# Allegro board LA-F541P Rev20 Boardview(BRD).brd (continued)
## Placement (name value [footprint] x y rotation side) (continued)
PC1910  4.7U_0402_6.3V6M  [C_0402]  48.62 10.21 180 top
PC1911  1U 25V K X5R 0402  [C_0402]  48.58 9.32 270 top
PC1912  1U 25V K X5R 0402  [C_0402]  47.69 9.32 270 top
PC1913  0.22U_0603_25V7K  [C_0603]  44.07 8.7 90 top
PC1914  10U_0603_25V6M  [C_0603]  33.83 27.81 90 bottom
PC1915  10U_0603_25V6M  [C_0603]  35.05 27.81 90 bottom
PC1916  10U_0603_25V6M  [C_0603]  35.05 27.81 90 top
PC1917  10U_0603_25V6M  [C_0603]  36.32 27.81 90 bottom
PC1918  10U_0603_25V6M  [C_0603]  37.59 27.81 90 bottom
PC1919  10U_0603_25V6M  [C_0603]  36.32 27.81 90 top
PC1920  10U_0603_25V6M  [C_0603]  33.83 27.81 90 top
PC1921  10U_0603_25V6M  [C_0603]  32.61 27.81 90 top
PC1922  10U_0603_25V6M  [C_0603]  32.61 27.81 90 bottom
PC1923  0.1U_0402_25V6  [C_0402]  43.82 24.21 270 bottom
PC1924  2200P_0402_50V7K  [C_0402]  43.82 21.51 90 bottom
PC1925  0.1U 25V K X5R 0402  [C_0402]  53.52 13.54 270 bottom
PC1926  1U_0603_25V6  [C_0603]  52.45 12.19 90 top
PC1927  1U_0402_6.3V6K  [C_0402]  41.71 10.16 0 top
PC1928  1U_0402_6.3V6K  [C_0402]  53.96 14.86 0 top
PC1929  0.22U_0603_25V7K  [C_0603]  43.5 12.45 180 top
PC1930  10U_0603_25V6M  [C_0603]  27 23.67 270 bottom
PC1931  10U_0603_25V6M  [C_0603]  28.45 25.91 0 bottom
PC1932  2200P_0402_50V7K  [C_0402]  31.48 17.1 270 bottom
PC1933  4700P_0402_25V7K  [C_0402]  42.67 19.43 180 top
PC1934  10P_0402_50V8J  [C_0402]  52.76 19.75 0 top
PC1935  0.1U_0402_25V6  [C_0402]  42.37 14.86 180 top
PC1936  680P_0402_50V7K  [C_0402]  38.48 6.73 0 top
PC1937  680P_0402_50V7K  [C_0402]  33.34 13.03 270 top
PC1938  1U 25V K X5R 0402  [C_0402]  42.37 15.88 180 top
PC1939  560P_0402_50V7K  [C_0402]  47.83 20.56 90 top
PC1940  0.1U_0402_25V6  [C_0402]  45.28 20.5 90 top
PC1941  0.012U_0402_16V7K  [C_0402]  48.76 20.56 90 top
PC1942  1U_0402_25V6K  [C_0402]  43.31 17.6 270 top
PC1943  0.22U_0402_25V6K  [C_0402]  42.37 18.42 180 top
PC1944  0.1U_0402_10V7K  [C_0402]  62.69 16.45 180 top
PC1945  0.1U_0402_25V6  [C_0402]  41.77 20.38 0 top
PC2000  22U_0603_6.3VAM  [C_0603]  175.85 92.39 90 bottom
PC2001  470U_D2_2VM_R4.5M~D  [C_D2]  156.08 100.59 180 bottom
PC2002  470U_D2_2VM_R4.5M~D  [C_D2]  158.22 95.89 0 bottom
PC2003  22U_0603_6.3VAM  [C_0603]  150.49 105.57 90 top
PC2004  1U_0201_6.3V6M  [C_0201]  156.22 73.23 0 top
PC2005  1U_0201_6.3V6M  [C_0201]  162.74 86.88 0 top
PC2006  1U_0201_6.3V6M  [C_0201]  160.81 85.9 180 top
PC2007  1U_0201_6.3V6M  [C_0201]  161.19 69.61 180 top
PC2008  1U_0201_6.3V6M  [C_0201]  167.76 69.59 0 top
PC2009  1U_0201_6.3V6M  [C_0201]  155.29 81.18 180 top
PC2010  22U_0603_6.3VAM  [C_0603]  146.8 105.71 90 top
PC2011  220U_D7_2VM_R6M  [C_EEFSS0D221R]  161.4 77.22 0 top
PC2012  22U_0603_6.3VAM  [C_0603]  161.25 80.46 180 top
PC2013  22U_0603_6.3VAM  [C_0603]  157.28 84.72 0 top
PC2014  22U_0603_6.3VAM  [C_0603]  157.28 74.21 0 top
PC2015  22U_0603_6.3VAM  [C_0603]  160.68 83.01 180 top
PC2016  22U_0603_6.3VAM  [C_0603]  166.17 80.49 180 top
PC2017  22U_0603_6.3VAM  [C_0603]  166.6 71.19 180 top
PC2018  22U_0603_6.3VAM  [C_0603]  161.77 71.19 180 top
PC2019  470U_D2_2VM_R4.5M~D  [C_D2]  118.14 76.76 180 bottom
PC2020  470U_D2_2VM_R4.5M~D  [C_D2]  123.19 74.96 270 bottom
PC2021  22U_0603_6.3VAM  [C_0603]  145.82 70.63 180 top
PC2022  22U_0603_6.3VAM  [C_0603]  120.14 71.18 270 top
PC2023  22U_0603_6.3VAM  [C_0603]  146.71 78.24 0 top
PC2024  22U_0603_6.3VAM  [C_0603]  145.76 78.2 180 top
PC2025  22U_0603_6.3VAM  [C_0603]  151.7 79.83 0 top
PC2026  22U_0603_6.3VAM  [C_0603]  151.69 81.08 0 top
PC2027  22U_0603_6.3VAM  [C_0603]  151.42 76.57 0 top
PC2028  220U_D7_2VM_R6M  [C_EEFSS0D221R]  154.33 100.59 180 top
PC2029  1U_0201_6.3V6M  [C_0201]  157.92 85.64 0 top
PC2030  1U_0201_6.3V6M  [C_0201]  162.8 81.38 0 top
PC2031  1U_0201_6.3V6M  [C_0201]  156.23 72.01 0 top
PC2032  1U_0201_6.3V6M  [C_0201]  163.08 70.25 0 top
PC2033  1U_0201_6.3V6M  [C_0201]  167.79 70.22 0 top
PC2034  1U_0201_6.3V6M  [C_0201]  156.21 71.43 0 top
PC2035  1U_0201_6.3V6M  [C_0201]  165.96 70.22 180 top
PC2036  1U_0201_6.3V6M  [C_0201]  161.15 70.29 180 top
PC2037  1U_0201_6.3V6M  [C_0201]  165.73 81.37 180 top
PC2038  1U_0201_6.3V6M  [C_0201]  161.27 83.92 180 top
PC2039  22U_0603_6.3VAM  [C_0603]  161.64 74.13 180 top
PC2040  22U_0603_6.3VAM  [C_0603]  162.37 97.79 0 top
PC2041  22U_0603_6.3VAM  [C_0603]  158.6 77.68 90 top
PC2042  1U_0201_6.3V6M  [C_0201]  162.75 86.31 0 top
PC2043  1U_0201_6.3V6M  [C_0201]  157.9 87.41 0 top
PC2044  1U_0201_6.3V6M  [C_0201]  156.22 69.54 0 top
PC2045  1U_0201_6.3V6M  [C_0201]  156.51 86.25 180 top
PC2046  1U_0201_6.3V6M  [C_0201]  157.58 81.48 0 top
PC2047  1U_0201_6.3V6M  [C_0201]  167.7 84.9 0 top
PC2048  1U_0201_6.3V6M  [C_0201]  165.93 84.19 180 top
PC2049  1U_0201_6.3V6M  [C_0201]  165.56 85.09 180 top
PC2050  1U_0201_6.3V6M  [C_0201]  160.82 84.69 180 top
PC2051  1U_0201_6.3V6M  [C_0201]  161.92 83.81 0 top
PC2052  1U_0201_6.3V6M  [C_0201]  157.9 86.23 0 top
PC2053  1U_0201_6.3V6M  [C_0201]  160.91 81.97 180 top
PC2054  1U_0201_6.3V6M  [C_0201]  167.71 84.2 0 top
PC2055  1U_0201_6.3V6M  [C_0201]  162.73 85.09 0 top
PC2056  1U_0201_6.3V6M  [C_0201]  156.22 72.64 0 top
PC2057  1U_0201_6.3V6M  [C_0201]  167.72 85.68 0 top
PC2058  1U_0201_6.3V6M  [C_0201]  167.63 86.83 0 top
PC2059  1U_0201_6.3V6M  [C_0201]  165.56 86.25 180 top
PC2060  1U_0201_6.3V6M  [C_0201]  165.57 86.85 180 top
PC2061  1U_0201_6.3V6M  [C_0201]  160.81 86.48 180 top
PC2062  1U_0201_6.3V6M  [C_0201]  160.94 81.38 180 top
PC2063  1U_0201_6.3V6M  [C_0201]  167.61 81.38 0 top
PC2064  1U_0201_6.3V6M  [C_0201]  162.74 85.7 0 top
PC2065  1U_0201_6.3V6M  [C_0201]  156.25 70.78 0 top
PC2066  1U_0201_6.3V6M  [C_0201]  161.92 84.39 0 top
PC2067  1U_0201_6.3V6M  [C_0201]  165.96 69.59 180 top
PC2068  1U_0201_6.3V6M  [C_0201]  157.89 86.83 0 top
PC2069  1U_0201_6.3V6M  [C_0201]  160.81 85.3 180 top
PC2070  1U_0201_6.3V6M  [C_0201]  156.24 70.15 0 top
PC2071  1U_0201_6.3V6M  [C_0201]  163.08 69.67 0 top
PC2072  1U_0201_6.3V6M  [C_0201]  165.58 85.67 180 top
PC2073  1U_0201_6.3V6M  [C_0201]  167.63 86.26 0 top
PC2074  1U_0201_6.3V6M  [C_0201]  152.08 85.82 0 top
PC2075  1U_0201_6.3V6M  [C_0201]  145.33 69.72 180 top
PC2076  1U_0201_6.3V6M  [C_0201]  152.02 69.74 0 top
PC2077  1U_0201_6.3V6M  [C_0201]  152.01 84.51 0 top
PC2078  1U_0201_6.3V6M  [C_0201]  151.94 83.26 0 top
PC2079  1U_0201_6.3V6M  [C_0201]  151.59 87.87 0 top
PC2080  1U_0201_6.3V6M  [C_0201]  145.25 68.73 270 top
PC2081  1U_0201_6.3V6M  [C_0201]  146.19 68.67 270 top
PC2082  1U_0201_6.3V6M  [C_0201]  153.21 69.74 0 top
PC2083  1U_0201_6.3V6M  [C_0201]  144.15 69.13 90 top
PC2084  1U_0201_6.3V6M  [C_0201]  147.06 68.69 270 top
PC2085  1U_0201_6.3V6M  [C_0201]  152.95 68.91 0 top
PC2086  22U_0603_6.3VAM  [C_0603]  162.37 99.06 0 top
PC2087  22U_0603_6.3VAM  [C_0603]  157.39 76.68 270 top
PC2088  22U_0603_6.3VAM  [C_0603]  162.37 100.33 0 top
PC2089  22U_0603_6.3VAM  [C_0603]  162.39 82.92 0 top
PC2090  22U_0603_6.3VAM  [C_0603]  151.72 105.55 90 top
PC2091  22U_0603_6.3VAM  [C_0603]  146.88 79.83 0 top
PC2092  22U_0603_6.3VAM  [C_0603]  146.58 76.55 0 top
PC2093  22U_0603_6.3VAM  [C_0603]  151.78 73.57 0 top
PC2094  22U_0603_6.3VAM  [C_0603]  146.86 81.08 0 top
PC2095  22U_0603_6.3VAM  [C_0603]  153.53 105.4 90 top
PC2096  22U_0603_6.3VAM  [C_0603]  162.36 80.49 0 top
PC2097  22U_0603_6.3VAM  [C_0603]  167.61 71.19 0 top
PC2098  22U_0603_6.3VAM  [C_0603]  167.18 80.49 0 top
PC2099  22U_0603_6.3VAM  [C_0603]  160.85 100.33 0 bottom
PC2100  22U_0603_6.3VAM  [C_0603]  160.85 99.06 0 bottom
PC2101  22U_0603_6.3VAM  [C_0603]  162.79 71.19 0 top
PC2102  22U_0603_6.3VAM  [C_0603]  160.85 101.6 0 bottom
PC2103  22U_0603_6.3VAM  [C_0603]  167.15 82.91 0 top
PC2104  22U_0603_6.3VAM  [C_0603]  167.61 72.43 0 top
PC2105  22U_0603_6.3VAM  [C_0603]  166.19 82.9 180 top
PC2106  22U_0603_6.3VAM  [C_0603]  162.79 72.42 0 top
PC2107  22U_0603_6.3VAM  [C_0603]  161.84 72.42 180 top
PC2108  22U_0603_6.3VAM  [C_0603]  167.42 74.07 0 top
PC2109  22U_0603_6.3VAM  [C_0603]  166.46 74.13 180 top
PC2110  22U_0603_6.3VAM  [C_0603]  162.65 74.13 0 top
PC2111  22U_0603_6.3VAM  [C_0603]  166.59 72.42 180 top
PC2112  22U_0603_6.3VAM  [C_0603]  158.66 76.68 270 top
PC2113  22U_0603_6.3VAM  [C_0603]  157.03 80.56 0 top
PC2114  22U_0603_6.3VAM  [C_0603]  145.34 105.74 90 top
PC2115  22U_0603_6.3VAM  [C_0603]  156.89 83.05 0 top
PC2116  22U_0603_6.3VAM  [C_0603]  144.03 105.77 90 top
PC2117  22U_0603_6.3VAM  [C_0603]  157.33 77.68 90 top
PC2118  22U_0603_6.3VAM  [C_0603]  123.95 71.18 270 top
PC2119  22U_0603_6.3VAM  [C_0603]  122.68 71.18 270 top
PC2120  22U_0603_6.3VAM  [C_0603]  121.41 71.18 270 top
PC2121  22U_0603_6.3VAM  [C_0603]  150.77 70.63 180 top
PC2122  22U_0603_6.3VAM  [C_0603]  146.96 70.63 0 top
PC2123  22U_0603_6.3VAM  [C_0603]  151.47 78.22 0 top
PC2124  22U_0603_6.3VAM  [C_0603]  150.45 78.22 180 top
PC2125  22U_0603_6.3VAM  [C_0603]  151.79 70.63 0 top
PC2126  22U_0603_6.3VAM  [C_0603]  151.75 72.29 0 top
PC2127  22U_0603_6.3VAM  [C_0603]  150.73 72.29 180 top
PC2128  22U_0603_6.3VAM  [C_0603]  146.92 72.29 0 top
PC2129  22U_0603_6.3VAM  [C_0603]  145.78 72.29 180 top
PC2130  22U_0603_6.3VAM  [C_0603]  150.64 73.57 180 top
PC2131  22U_0603_6.3VAM  [C_0603]  150.69 79.83 180 top
PC2132  22U_0603_6.3VAM  [C_0603]  150.67 81.08 180 top
PC2133  22U_0603_6.3VAM  [C_0603]  150.4 76.57 180 top
PC2134  22U_0603_6.3VAM  [C_0603]  146.83 73.57 0 top
PC2135  22U_0603_6.3VAM  [C_0603]  145.69 73.57 180 top
PC2136  22U_0603_6.3VAM  [C_0603]  145.57 76.55 180 top
PC2137  22U_0603_6.3VAM  [C_0603]  145.86 79.83 180 top
PC2138  22U_0603_6.3VAM  [C_0603]  145.85 81.08 180 top
PC2139  22U_0603_6.3VAM  [C_0603]  171.58 76.14 180 top
PC2140  22U_0603_6.3VAM  [C_0603]  171.58 74.93 180 top
PC2141  22U_0603_6.3VAM  [C_0603]  171.58 77.34 180 top
PC2142  22U_0603_6.3VAM  [C_0603]  171.58 78.61 180 top
PC2143  22U_0603_6.3VAM  [C_0603]  171.66 73.69 180 top
PC2144  22U_0603_6.3VAM  [C_0603]  117.86 88.2 270 top
PC2145  22U_0603_6.3VAM  [C_0603]  116.59 88.2 270 top
PC2146  22U_0603_6.3VAM  [C_0603]  117.86 88.2 270 bottom
PC2147  22U_0603_6.3VAM  [C_0603]  115.32 88.2 270 bottom
PC2148  22U_0603_6.3VAM  [C_0603]  116.59 88.2 270 bottom
PC2149  22U_0603_6.3VAM  [C_0603]  115.32 88.2 270 top
PC2150  22U_0603_6.3VAM  [C_0603]  170.82 92.39 90 bottom
PC2151  22U_0603_6.3VAM  [C_0603]  172.09 92.39 90 bottom
PC2152  22U_0603_6.3VAM  [C_0603]  173.36 92.39 90 bottom
PC2153  22U_0603_6.3VAM  [C_0603]  174.63 92.39 90 bottom
PD100  AZ5125-01H.R7G_SOD523-2  [AZ5125-01HPR7G_SOD523-2]  28.32 82.05 90 top
PD101  -  [TVNST52302AB0_SOT523-3]  14.1 10.23 0 top
PD102  -  [TVNST52302AB0_SOT523-3]  21.34 3.11 180 top
PD200  SDT8A100P5-13D_POWERDI5-3  [PDS1040-13_POWERDI5-3]  15.24 20.07 90 bottom
PD201  SDT8A100P5-13D_POWERDI5-3  [PDS1040-13_POWERDI5-3]  20.24 20.07 90 bottom
PD202  -  [RB751V-40_SOD323-2]  21.78 10.67 180 top
PD203  -  [RB520SM-30T2R_EMD2-2]  66.97 22.54 225 top
PD204  -  [RB520SM-30T2R_EMD2-2]  64.83 25.33 225 top
PD1900  -  [RB751V-40_SOD323-2]  57.28 16.38 270 top
PD1902  -  [RB751V-40_SOD323-2]  59.79 15.93 270 top
PD1903  -  [BAT54CW_SOT323-3]  62.5 11.99 0 top
PD1904  SMF4L22A SOD123FL-2  [SMF22A-SOD123FL-2-S]  58.01 6.59 270 bottom
PH1100  470K_0402_5%_ TSM0B474J4702RE  [R_0402]  105.16 85.66 270 bottom
PH1101  10K_0402_5%_B25/50 4250K  [R_0402]  114.99 92.67 180 bottom
PH1102  10K_0402_5%_B25/50 4250K  [R_0402]  121.22 85.92 180 bottom
PH1103  10K_0402_5%_B25/50 4250K  [R_0402]  146.53 101.79 0 bottom
PH1104  470K_0402_5%_ TSM0B474J4702RE  [R_0402]  145.29 103.04 180 bottom
PJP200  -  [JUMP_43X118]  25.86 27.93 180 top
PJP400  -  [JUMP_43X118]  318.58 11.3 0 top
PJP402  PAD-OPEN 4X4M  [JUMP_43X118]  324.71 25.33 180 top
PJP403  PAD-OPEN 4X4M  [JUMP_43X118]  318.02 5.71 180 top
PJP500  -  [JUMP_43X118]  120.83 7.03 90 bottom
PJP600  -  [JUMP_43X118]  279.59 31.28 180 bottom
PJP601  PAD-OPEN1X1M  [JUMP_43X39]  283.15 30.93 0 bottom
PJP602  PAD-OPEN 3X3M  [JUMP_43X79]  283.02 29.4 270 top
PJP603  PAD-OPEN 4X4M  [JUMP_43X118]  256.73 25.7 270 bottom
PJP701  -  [JUMP_43X118]  216.24 118.24 0 bottom
PJP702  -  [JUMP_43X118]  216.24 118.24 0 top
PJP800  -  [JUMP_43X118]  117.22 63.95 0 bottom
PJP900  PAD-OPEN1X1M  [JUMP_43X39]  224.64 116.21 0 bottom
PJP1301  -  [JUMP_43X118]  109.28 98.74 90 bottom
PJP1302  PAD-OPEN 3X3M  [JUMP_43X79]  115.22 11.89 180 bottom
PJP1303  PAD-OPEN 3X3M  [JUMP_43X79]  118.49 12.53 90 bottom
PJP1600  -  [JUMP_43X118]  244.6 97.32 270 bottom
PJP1604  PAD-OPEN 3X3M  [JUMP_43X79]  164.09 51.22 270 top
PL104  BLM15AG102SN1D_2P  [MURAT_BLM15AG102SN1D_2P]  26.39 82.44 90 top
PL105  HCB2012KF-800T50_2P  [TAI-T_HCB2012KF-800T50_2P]  25.78 86.77 0 bottom
PL106  HCB2012KF-800T50_2P  [TAI-T_HCB2012KF-800T50_2P]  25.78 88.63 0 bottom
PL107  HCB2012KF-800T50_2P  [TAI-T_HCB2012KF-800T50_2P]  30.32 16.68 180 bottom
PL108  HCB2012KF-800T50_2P  [TAI-T_HCB2012KF-800T50_2P]  26.62 18.97 270 bottom
PL200  HCB2012KF-800T50_2P  [TAI-T_HCB2012KF-800T50_2P]  30.9 28 180 top
PL201  HCB2012KF-800T50_2P  [TAI-T_HCB2012KF-800T50_2P]  30.9 29.83 180 top
PL400  3.3UH_PCMB063T-3R3MS_6.5A_20%  [CYNTE_PCMB063T-3R3MS_2P]  331.3 28.52 0 top
PL401  2.2UH_PCMB103T-2R2MS_13A_20%  [CYNTE_PCMB103T-2R2MS_2P]  337.82 7.45 180 top
PL402  HCB2012KF-800T50_2P  [TAI-T_HCB2012KF-800T50_2P]  318.26 14.83 0 top
PL403  HCB2012KF-800T50_2P  [TAI-T_HCB2012KF-800T50_2P]  318.26 16.7 0 top
PL500  HCB2012KF-800T50_2P  [TAI-T_HCB2012KF-800T50_2P]  138.98 12.46 270 bottom
PL501  1UH_PCMB053T-1R0MS_7A_20%  [CYNTE_PCMB053T-1R0MS_2P]  129.68 6.49 180 bottom
PL600  1UH_PCMB063T-1R0MS_12A_20%  [CYNTE_PCMB063T-1R0MS_2P]  262.53 32.26 0 bottom
PL601  HCB2012KF-800T50_2P  [TAI-T_HCB2012KF-800T50_2P]  279.56 27.75 180 bottom
PL700  0.82UH_MMD-06CZ-R82M-V1L_13A_20%  [L_7X7X3_M_2P]  201.95 116.33 0 bottom
PL777  HCB2012KF-800T50_2P  [TAI-T_HCB2012KF-800T50_2P]  196.72 113.25 270 top
PL800  HCB2012KF-800T50_2P  [TAI-T_HCB2012KF-800T50_2P]  105.39 56.9 0 bottom
PL801  1UH_PCMB053T-1R0MS_7A_20%  [CYNTE_PCMB053T-1R0MS_2P]  112.9 60.64 90 bottom
PL900  HCB2012KF-800T50_2P  [TAI-T_HCB2012KF-800T50_2P]  247.91 113.41 90 bottom
PL901  1UH_PCMB053T-1R0MS_7A_20%  [CYNTE_PCMB053T-1R0MS_2P]  235.62 114.97 180 bottom
PL1000  HCB2012KF-800T50_2P  [TAI-T_HCB2012KF-800T50_2P]  166.29 106.7 180 top
PL1001  HCB2012KF-800T50_2P  [TAI-T_HCB2012KF-800T50_2P]  166.29 108.56 180 top
PL1002  0.22UH_MMD-06DZIR22MEM2L_32A_20%  [MAG_MMD-06DZIR22MEM2L_2P]  176.17 100.46 0 bottom
PL1003  0.22UH_MMD-06DZIR22MEM2L_32A_20%  [MAG_MMD-06DZIR22MEM2L_2P]  176.86 108.9 0 bottom
PL1200  0.22UH_MMD-06DZIR22MEM2L_32A_20%  [MAG_MMD-06DZIR22MEM2L_2P]  145.61 111.68 270 bottom
PL1201  0.22UH_MMD-06DZIR22MEM2L_32A_20%  [MAG_MMD-06DZIR22MEM2L_2P]  152.97 111.58 270 bottom
PL1202  0.22UH_MMD-06DZIR22MEM2L_32A_20%  [MAG_MMD-06DZIR22MEM2L_2P]  160.33 111.2 270 bottom
PL1203  HCB2012KF-800T50_2P  [TAI-T_HCB2012KF-800T50_2P]  127.46 105.86 90 bottom
PL1204  HCB2012KF-800T50_2P  [TAI-T_HCB2012KF-800T50_2P]  129.3 105.86 90 bottom
PL1300  0.22UH_MMD-06DZIR22MEM2L_32A_20%  [MAG_MMD-06DZIR22MEM2L_2P]  112.99 82.86 0 bottom
PL1301  0.22UH_MMD-06DZIR22MEM2L_32A_20%  [MAG_MMD-06DZIR22MEM2L_2P]  112.12 70.74 0 bottom
PL1303  HCB2012KF-800T50_2P  [TAI-T_HCB2012KF-800T50_2P]  106.88 67.52 90 bottom
PL1304  HCB2012KF-800T50_2P  [TAI-T_HCB2012KF-800T50_2P]  108.73 67.52 90 bottom
PL1305  HCB2012KF-800T50_2P  [TAI-T_HCB2012KF-800T50_2P]  105.58 98.35 270 bottom
PL1306  0.47UH_MMD05CZR47M_12A_20%  [MAG_MMD05CZR47M_4P]  108.4 89.27 0 bottom
PL1500  0.22UH_MMD-06DZIR22MEM2L_32A_20%  [MAG_MMD-06DZIR22MEM2L_2P]  190.5 100.61 0 bottom
PL1501  HCB2012KF-800T50_2P  [TAI-T_HCB2012KF-800T50_2P]  197.12 107.66 90 top
PL1502  HCB2012KF-800T50_2P  [TAI-T_HCB2012KF-800T50_2P]  198.97 108.09 90 top
PL1600  HCB2012KF-800T50_2P  [TAI-T_HCB2012KF-800T50_2P]  247.92 111.97 270 bottom
PL1601  1UH_1239AS-H-1R0M-P2_3A_20%  [TOKO_1239AS-H-1R0M-P2_2P]  244.22 101.46 270 bottom
PL1900  1UH +-20% 6.6A 5X5X3 MOLDING, A.3  [MAGLA_MMD-05CZ-1R0M-M7L_2P]  51.14 5.4 0 bottom
PL1901  1UH_MMD-10DZ-1R0M-X1A_18A_20%  [MAG_MMD-10DZ-1R0M-X1A_2P]  36.32 4.78 90 bottom
PQ100  -  [FDV301N-G_SOT23-3]  23.5 82.78 0 top
PQ101  -  [MMBT3904WH_SOT323-3]  24.51 87.72 180 top
PQ200  AON7409_DFN8-5  [FDMC6679AZ_MLP8-5]  14.28 28.45 0 bottom
PQ201  AON7409_DFN8-5  [FDMC6679AZ_MLP8-5]  11.41 20.32 180 bottom
PQ202  -  [AO3409_SOT23-3]  9.91 22.2 180 top
PQ203  -  [DMN65D8LDW-7_SOT363-6]  15.51 23.1 90 top
PQ204  -  [DMN65D8LW-7_SOT323-3]  9.05 24.75 90 top
PQ205  -  [DMN65D8LW-7_SOT323-3]  14.3 31.72 0 bottom
PQ206  -  [DMN65D8LW-7_SOT323-3]  16.95 29.72 270 top
PQ207  AON7409_DFN8-5  [FDMC6679AZ_MLP8-5]  23.88 26.67 90 bottom
PQ208  AON7409_DFN8-5  [FDMC6679AZ_MLP8-5]  21.18 28.45 270 bottom
PQ209  AON7409_DFN8-5  [FDMC6679AZ_MLP8-5]  25.4 22.23 180 bottom
PQ210  -  [AO3409_SOT23-3]  27.31 21.97 0 top
PQ211  -  [AO3409_SOT23-3]  17.3 22.12 180 top
PQ212  -  [DMN65D8LDW-7_SOT363-6]  29.96 20.64 0 top
PQ213  -  [DMN65D8LDW-7_SOT363-6]  17.64 24.02 0 top
PQ214  -  [DMN65D8LDW-7_SOT363-6]  19.29 15.94 0 top
PQ215  -  [DMN65D8LDW-7_SOT363-6]  18.23 29.99 270 top
PQ216  -  [DMN65D8LDW-7_SOT363-6]  20.34 13.9 180 top
PQ217  -  [DMN65D8LW-7_SOT323-3]  22.99 14.44 0 top
PQ219  -  [2N7002KDW_SOT363-6]  78.06 32.97 315 top
PQ220  DMN65D8LDW-7 2N SOT363-6  [DMN66D0LDW-7_SOT363-6]  59.38 17.25 270 bottom
PQ221  DMN65D8LDW-7 2N SOT363-6  [DMN66D0LDW-7_SOT363-6]  57.82 13.19 90 bottom
PQ222  S TR AO7401 1P SC70-3  [SI1303DL-T1-E3_SOT323-3]  74.1 26.84 315 top
PQ223  DMN65D8LDW-7 2N SOT363-6  [DMN66D0LDW-7_SOT363-6]  58.77 21.01 270 bottom
PQ224  -  [DMN65D8LW-7_SOT323-3]  62.72 16.33 270 bottom
PQ225  -  [DMN65D8LW-7_SOT323-3]  71.24 24.79 135 top
PQ226  S TR AO7401 1P SC70-3  [SI1303DL-T1-E3_SOT323-3]  75.24 33.68 135 top
PQ227  DMN65D8LDW-7 2N SOT363-6  [DMN66D0LDW-7_SOT363-6]  54.51 17.16 270 bottom
PQ400  -  [AON7408L_DFN8-5]  332.42 24.07 180 top
PQ401  -  [AON6380_DFN5X6-8-5]  326.97 13.5 0 top
PQ402  -  [AON7506_DFN3X3-8-5]  334.58 21.02 0 top
PQ403  -  [AON6796_DFN5X6-8-5]  337.76 18.98 180 top
PQ600  -  [AON7406L_DFN8-5]  271.49 31.52 90 bottom
PQ601  -  [AON7516_DFN8-5]  273.57 28.79 270 bottom
PQ700  -  [AON6962_DFN5X6D-8-7]  199.01 113.75 180 bottom
PQ701  DMN53D0LDW-7 2N SOT363-6  [2N7002DW-7-F_SOT363-6]  184.39 118.62 0 top
PQ1000  AON6354_N_DFN56-8-5  [Q_N_DFN56-8-5]  173.11 105.54 270 bottom
PQ1001  AON6314_N_DFN56-8-5  [Q_N_DFN56-8-5]  167.76 95.63 90 bottom
PQ1002  AON6354_N_DFN56-8-5  [Q_N_DFN56-8-5]  173.87 111.63 270 bottom
PQ1003  AON6314_N_DFN56-8-5  [Q_N_DFN56-8-5]  177.09 118.82 0 bottom
PQ1007  AON6314_N_DFN56-8-5  [Q_N_DFN56-8-5]  167.76 102.03 270 top
PQ1008  AON6314_N_DFN56-8-5  [Q_N_DFN56-8-5]  180.9 118.82 180 top
PQ1300  -  [AONH36334_DFN3X3A8-10]  106.92 92.85 90 bottom
PQ1500  AON6354_N_DFN56-8-5  [Q_N_DFN56-8-5]  192.4 105.16 90 bottom
PQ1501  AON6314_N_DFN56-8-5  [Q_N_DFN56-8-5]  186.31 110.49 0 bottom
PQ1900  -  [AON6380_DFN5X6-8-5]  42.81 5.97 270 top
PQ1901  AON6314_DFN5X6-8  [AON6232A_DFN5X6-8-5]  42.04 18.6 180 bottom
PQ1902  -  [AON6380_DFN5X6-8-5]  42.87 2.73 90 bottom
PQ1903  AON6314_DFN5X6-8  [AON6232A_DFN5X6-8-5]  48.07 12.87 270 bottom
PQ1904  -  [AON6380_DFN5X6-8-5]  49.78 18.92 270 bottom
PQ1905  -  [AON7405_DFN8-5]  28.42 21.38 0 bottom
PQ1906  -  [DMN65D8LW-7_SOT323-3]  56.77 21.21 180 top
PR100  0_0402_5%  [R_0402]  23.57 86.49 180 top
PR101  2.2K_0402_5%  [R_0402]  21.13 88.01 0 top
PR102  33_0402_5%  [R_0402]  27.28 83.33 270 top
PR103  100K_0402_5%  [R_0402]  23.57 87.25 180 top
PR104  10K_0402_5%  [R_0402]  24.44 86.49 0 top
PR105  15K_0402_5%  [R_0402]  22.86 88.06 90 top
PR106  100_0402_5%  [R_0402]  14.86 6.81 180 top
PR108  100_0402_5%  [R_0402]  14.86 7.57 180 top
PR111  100_0402_5%  [R_0402]  19.69 6.05 270 top
PR112  10K_0402_5%  [R_0402]  19.89 4.32 180 top
PR200  300K_0402_5%  [R_0402]  13.59 19.94 90 top
PR201  499K_0402_1%  [R_0402]  10.29 19.31 180 bottom
PR202  1M_0402_5%  [R_0402]  15.24 30.61 0 bottom
PR203  100K_0402_5%  [R_0402]  14.48 27.05 90 top
PR204  100K_0402_5%  [R_0402]  14.48 20.83 90 top
PR205  49.9K_0402_1%  [R_0402]  7.88 24.26 90 top
PR206  100K_0402_5%  [R_0402]  15.37 26.29 270 top
PR207  1.8M_0402_1%  [R_0402]  33.94 4.55 0 top
PR208  1K_0402_1%  [R_0402]  29.73 1.6 0 top
PR209  1M_0402_5%  [R_0402]  16.13 31.37 180 bottom
PR210  0_0402_5%  [R0402_0OHM]  16.38 23.8 90 top
PR211  240K_0402_1%  [R_0402]  34.85 3.71 180 top
PR212  102K_0402_1%  [R_0402]  34.79 2.92 180 top
PR213  0_0402_5%  [R0402_0OHM]  12.3 22.26 90 top
PR214  0_0402_5%  [R0402_0OHM]  17.02 30.56 90 bottom
PR215  0_0402_5%  [R0402_0OHM]  17.78 30.56 90 bottom
PR216  0_0402_5%  [R0402_0OHM]  12.55 31.19 90 bottom
PR217  100K_0402_5%  [R_0402]  12.32 24.69 90 top
PR218  0_0402_5%  [R0402_0OHM]  14.61 25.38 90 top
PR219  24K_0402_1%  [R_0402]  33.08 4.7 90 top
PR220  84.5K_0402_1%  [R_0402]  33.09 3.79 270 top
PR221  0_0402_5%  [R0402_0OHM]  19 31.5 180 top
PR222  100K_0402_5%  [R_0402]  17.35 31.5 180 top
PR223  0_0402_5%  [R0402_0OHM]  14.78 31.5 0 top
PR224  100K_0402_5%  [R_0402]  17.83 29.72 0 bottom
PR225  300K_0402_5%  [R_0402]  27.56 25.78 0 top
PR226  300K_0402_5%  [R_0402]  19.66 20.02 270 top
PR227  100K_0402_5%  [R_0402]  28.96 27.43 0 bottom
PR228  499K_0402_1%  [R_0402]  22.56 27.43 180 top
PR229  499K_0402_1%  [R_0402]  22.81 25.27 180 top
PR230  499K_0402_1%  [R_0402]  20.7 21.13 90 top
PR231  100K_0402_5%  [R_0402]  29.39 19.69 0 top
PR232  100K_0402_5%  [R_0402]  29.64 23.52 0 top
PR233  100K_0402_5%  [R_0402]  20.42 19.79 270 top
PR234  330K_0402_1%  [R_0402]  28.57 7.42 90 top
PR235  49.9K_0402_1%  [R_0402]  18.72 23.12 0 top
PR236  100K_0402_5%  [R_0402]  21.46 19.64 270 top
PR237  49.9K_0402_1%  [R_0402]  19 26.8 180 top
PR238  0_0402_5%  [R0402_0OHM]  21.59 15.67 90 top
PR239  0_0402_5%  [R0402_0OHM]  16.38 26.42 270 top
PR240  49.9K_0402_1%  [R_0402]  21.92 29.85 180 top
PR241  100K_0402_5%  [R_0402]  16.43 27.18 0 top
PR242  0_0402_5%  [R0402_0OHM]  20.07 24.97 270 top
PR243  0_0402_5%  [R0402_0OHM]  21.46 20.37 90 top
PR244  160K_0402_1%  [R_0402]  29.59 10.82 270 top
PR245  0_0402_5%  [R0402_0OHM]  25.14 8.32 270 top
PR246  100K_0402_5%  [R_0402]  17.35 28.07 180 top
PR247  1M_0402_5%  [R_0402]  25.53 14.02 90 top
PR248  0_0402_5%  [R_0402]  24.77 14.02 90 top
PR249  330K_0402_1%  [R_0402]  27.68 7.44 90 top
PR250  0_0402_5%  [R0402_0OHM]  22.4 15.68 90 top
PR251  100K_0402_1%  [R_0402]  22.86 5.59 0 top
PR252  0_0402_5%  [R0402_0OHM]  23.18 15.68 90 top
PR253  0_0402_5%  [R0402_0OHM]  18.09 27.56 0 top
PR254  100K_0402_1%  [R_0402]  26.92 8.32 270 top
PR255  100K_0402_1%  [R_0402]  28.59 9.84 90 top
PR256  0_0402_5%  [R0402_0OHM]  25.6 13.21 180 top
PR257  100K_0402_5%  [R_0402]  24.69 12.45 0 top
PR258  0_0402_5%  [R0402_0OHM]  24.69 11.69 0 top
PR259  100K_0402_5%  [R_0402]  23.96 15.77 270 top
PR260  0_0402_5%  [R0402_0OHM]  23.04 11.18 0 top
PR261  10K_0402_5%  [R_0402]  20.3 14.81 180 top
PR262  0_0402_5%  [R0402_0OHM]  21.17 14.82 0 top
PR263  10K_0402_1%  [R_0402]  78.84 29.89 45 top
PR265  100K_0402_5%  [R_0402]  56.52 15.75 270 bottom
PR266  0_0805_5%  [R0805_0OHM]  76.01 30.92 45 top
PR267  100K_0402_5%  [R_0402]  56.84 14.04 180 bottom
PR268  0_0402_5%  [R0402_0OHM]  55.88 13.21 0 bottom
PR269  0_0402_5%  [R0402_0OHM]  56.39 17.4 270 bottom
PR270  100K_0402_5%  [R_0402]  61.66 15.74 90 bottom
PR271  0_0201_5%  [R_0201]  72.16 22.7 225 top
PR272  0_0402_5%  [R0402_0OHM]  60.39 15.74 90 bottom
PR273  100K_0402_5%  [R_0402]  56.75 21.97 0 bottom
PR274  100K_0402_5%  [R_0402]  59.69 20.07 0 bottom
PR275  100K_0201_1%  [R_0201]  73.63 31.49 315 top
PR276  300K_0402_5%  [R_0402]  72.91 27.26 135 top
PR277  0_0402_5%  [R_0402]  55.07 20.33 0 bottom
PR278  0_0402_5%  [R0402_0OHM]  55.08 19.54 0 bottom
PR279  100K_0402_5%  [R_0402]  53.86 18.12 90 bottom
PR280  300K_0402_5%  [R_0402]  69.14 22.29 135 top
PR282  100K_0402_5%  [R_0402]  53.72 14.86 0 bottom
PR283  0_0402_5%  [R_0402]  55.57 21.13 90 bottom
PR284  0_0402_5%  [R0402_0OHM]  52.2 19.05 270 bottom
PR285  0_0402_5%  [R_0402]  53.09 19.05 270 bottom
PR288  1M_0201_1%  [R_0201]  76.94 29.17 135 top
PR289  0_0805_5%  [R0805_0OHM]  71.85 30.29 315 top
PR290  0_0201_5%  [R_0201]  73.11 34.2 45 top
PR295  0_0201_5%  [R_0201]  71.32 23.55 315 top
PR326  2.2K_0402_5%  [R_0402]  346.97 26.8 270 top
PR400  0_0402_5%  [R0402_0OHM]  348.88 22.48 180 bottom
PR401  68.1K_0402_1%  [R_0402]  348.87 23.37 180 top
PR402  160K_0402_1%  [R_0402]  348.03 19.43 0 top
PR403  100K_0402_1%  [R_0402]  348.87 22.48 180 top
PR404  102K_0402_1%  [R_0402]  348.03 20.32 0 top
PR405  21.5K_0402_1%  [R_0402]  346.97 24.91 270 top
PR406  13.3K_0402_1%  [R_0402]  348.03 18.54 0 top
PR407  0_0402_5%  [R0402_0OHM]  345.12 24.91 270 top
PR408  0_0402_5%  [R0402_0OHM]  346.08 24.91 270 top
PR409  0_0402_5%  [R0402_0OHM]  347.98 17.64 90 bottom
PR410  200_0402_1%  [R_0402]  348.03 17.59 0 top
PR411  2.2_0603_5%  [R_0603]  342.27 24.58 0 top
PR412  2.2_0603_5%  [R_0603]  341.89 17.72 0 top
PR413  4.7_1206_5%  [R_1206]  336.93 33.02 180 top
PR414  4.7_1206_5%  [R_1206]  339.82 12.92 90 top
PR415  0_0402_5%  [R0402_0OHM]  340.58 22.47 180 top
PR428  100K_0402_5%  [R_0402]  345.12 24.91 270 bottom
PR500  100K_0402_5%  [R_0402]  137.56 4.45 180 bottom
PR501  0_0402_5%  [R0402_0OHM]  132.34 9.7 180 bottom
PR502  4.7_1206_5%  [R_1206]  130.37 2.8 180 bottom
PR503  0_0402_5%  [R_0402]  135.58 3.16 90 bottom
PR504  90.9K_0402_1%  [R_0402]  133.1 1.58 0 bottom
PR505  1M_0402_1%  [R_0402]  135.38 5.46 90 top
PR506  100K_0402_5%  [R_0402]  133.35 5.92 270 top
PR507  121K_0402_1%  [R_0402]  134.75 3.18 0 top
PR508  0_0402_5%  [R_0402]  134.72 4.05 0 top
PR521  0_0402_5%  [R0402_0OHM]  136.65 3.68 0 bottom
PR600  2.2_0603_5%  [R_0603]  283.15 29.15 0 bottom
PR601  7.87K_0402_1%  [R_0402]  288.99 26.99 180 bottom
PR602  4.7_1206_5%  [R_1206]  269.43 27.37 180 bottom
PR603  5.1_0603_5%  [R_0603]  289.52 25.77 90 top
PR604  16.2K_0402_1%  [R_0402]  291.85 31.62 90 top
PR605  1M_0402_1%  [R_0402]  292.22 26.95 180 bottom
PR606  0_0402_5%  [R0402_0OHM]  291.83 28.06 90 bottom
PR607  27K_0402_1%  [R_0402]  292.61 31.62 90 bottom
PR608  0_0402_5%  [R0402_0OHM]  292.75 29.85 180 bottom
PR609  100K_0402_5%  [R_0402]  291.8 27.88 180 top
PR610  0_0402_5%  [R_0402]  289.97 31.08 90 top
PR651  0_0402_5%  [R0402_0OHM]  291.75 27.05 180 top
PR700  2.2_0603_5%  [R_0603]  189.68 112.27 180 top
PR701  2.2_0201_1%  [R_0201]  190.29 120.91 180 top
PR702  4.7_1206_5%  [R_1206]  205.87 116.78 90 top
PR703  12K_0201_1%  [R_0201]  199.05 119.76 180 top
PR704  383K_0402_1%  [R_0402]  191 120.52 0 top
PR705  100K_0402_1%  [R_0402]  190.96 115.7 180 top
PR706  2.2_0603_5%  [R_0603]  197.68 117.03 270 top
PR707  8.66K_0402_1%  [R_0402]  192.66 113.87 270 top
PR708  10K_0201_1%  [R_0201]  197.87 119.8 270 top
PR709  0_0201_5%  [R_0201]  198.54 118.62 180 top
PR710  10K_0201_1%  [R_0201]  194.46 119.76 0 top
PR711  10_0402_5%  [R_0402]  189.61 117.02 90 top
PR712  30K_0201_1%  [R_0201]  186.69 119.88 90 top
PR713  68.1K_0402_1%  [R_0402]  186.61 119.13 0 top
PR715  10K_0402_5%  [R_0402]  182.42 120.71 0 top
PR717  0_0402_5%  [R0402_0OHM]  186.64 117.6 180 top
PR718  0_0201_5%  [R_0201]  190.37 116.93 90 top
PR800  0_0402_5%  [R0402_0OHM]  110.67 58.8 0 bottom
PR801  4.7_1206_5%  [R_1206]  109.35 60.52 90 top
PR803  100_0402_1%  [R_0402]  108.28 66.42 180 bottom
PR804  1M_0402_1%  [R_0402]  104.98 62.74 180 bottom
PR805  36.5K_0402_1%  [R_0402]  106.94 64.69 90 bottom
PR806  0_0402_5%  [R0402_0OHM]  106.63 66.42 180 bottom
PR807  100K_0402_5%  [R_0402]  104.06 65.79 0 bottom
PR808  0_0402_5%  [R_0402]  104.98 65.03 180 bottom
PR809  62K_0402_1%  [R_0402]  106.17 64.69 90 bottom
PR810  0_0402_5%  [R0402_0OHM]  106.6 65.79 0 top
PR811  100_0402_1%  [R_0402]  107.52 65.03 180 top
PR851  0_0402_5%  [R0402_0OHM]  104.81 61.98 180 top
PR852  100K_0402_5%  [R_0402]  104.94 60.22 90 top
PR900  0_0402_5%  [R0402_0OHM]  239.98 116.59 180 top
PR901  4.7_1206_5%  [R_1206]  232.6 115.57 0 top
PR902  0_0402_5%  [R0402_0OHM]  246.13 113.62 270 bottom
PR903  0_0402_5%  [R0402_0OHM]  245.42 111.96 270 bottom
PR904  100K_0402_1%  [R_0402]  240.41 111.05 90 top
PR905  0_0402_5%  [R_0402]  245.37 113.62 270 bottom
PR906  1M_0402_1%  [R_0402]  243.59 111.96 270 bottom
PR907  0_0402_5%  [R_0402]  246.18 111.05 90 bottom
PR908  133K_0402_1%  [R_0402]  241.3 111.96 270 bottom
PR909  100K_0402_5%  [R_0402]  242.83 111.05 90 bottom
PR910  0_0402_5%  [R0402_0OHM]  242.06 111.96 270 bottom
PR951  100K_0402_5%  [R_0402]  247.15 115.95 180 top
PR952  0_0402_5%  [R0402_0OHM]  244.57 115.95 0 top
PR1000  10K_0402_1%  [R_0402]  164.24 117.09 0 bottom
PR1001  22.6K_0402_1%  [R_0402]  164.83 116.29 180 bottom
PR1002  169K_0402_1%  [R_0402]  165.14 116.4 180 top
PR1003  0_0402_5%  [R0402_0OHM]  164.33 117.87 0 bottom
PR1004  2.2K_0402_5%  [R_0402]  164.55 114.83 180 bottom
PR1005  20.5K_0402_1%  [R_0402]  169.62 118.58 90 bottom
PR1006  4.32K_0402_1%  [R_0402]  166.28 118.63 90 bottom
PR1007  6.19K_0402_1%  [R_0402]  165.52 119.54 270 bottom
PR1008  16.5K_0402_1%  [R_0402]  167.04 118.63 90 bottom
PR1009  10_1206_5%  [R_1206]  175.52 99.25 90 top
PR1010  2.2_0603_5%  [R_0603]  163.96 113.92 270 bottom
PR1011  309_0402_1%  [R_0402]  163.22 120.8 180 top
PR1012  2.2_0603_5%  [R_0603]  166.88 111.75 270 bottom
PR1013  412K_0402_1%  [R_0402]  170.47 119.42 270 bottom
PR1014  20_0402_1%  [R_0402]  173.05 118.68 180 bottom
PR1015  2.2_0603_5%  [R_0603]  171.83 114.43 90 top
PR1016  100_0402_5%  [R_0402]  179.02 110.37 180 top
PR1017  0_0402_5%  [R0402_0OHM]  171.92 113.24 0 bottom
PR1018  0_0402_5%  [R0402_0OHM]  172.71 117.21 180 bottom
PR1019  10K_0402_5%  [R_0402]  171.92 114.01 0 bottom
PR1020  10_1206_5%  [R_1206]  174.96 114.3 90 top
PR1021  0_0402_5%  [R0402_0OHM]  172.71 116.44 180 bottom
PR1022  191K_0402_1%  [R_0402]  171.92 114.77 0 bottom
PR1023  100_0402_5%  [R_0402]  179.02 111.13 180 top
PR1100  6.81K_0402_1%  [R_0402]  111.13 110.49 0 bottom
PR1101  1_0402_5%  [R_0402]  117.54 112.59 270 bottom
PR1102  0_0402_5%  [R0402_0OHM]  118.43 112.59 270 bottom
PR1103  100_0402_1%  [R_0402]  116.8 109.32 180 bottom
PR1104  110K_0402_1%  [R_0402]  111.13 109.54 0 bottom
PR1105  10.2K_0402_1%  [R_0402]  111.13 108.59 0 top
PR1106  27.4K_0402_1%  [R_0402]  108.78 107.7 0 bottom
PR1107  165K_0402_1%  [R_0402]  122.44 111.7 90 top
PR1108  1.87K_0402_1%  [R_0402]  121.55 111.7 90 top
PR1109  28K_0402_1%  [R_0402]  120.59 111.7 90 top
PR1110  110K_0402_1%  [R_0402]  119.7 111.7 90 top
PR1111  3.6K_0402_1%  [R_0402]  111.13 107.63 0 bottom
PR1112  1K_0402_1%  [R_0402]  108.83 106.74 0 top
PR1113  2.1K_0402_1%  [R_0402]  109.73 104.97 90 top
PR1114  1.91K_0402_1%  [R_0402]  113.92 112.59 270 top
PR1115  1.1K_0402_1%  [R_0402]  122.56 109.41 0 top
PR1116  48.7K_0402_1%  [R_0402]  123.31 111.32 0 top
PR1117  1K_0402_1%  [R_0402]  124.84 109.4 90 top
PR1118  0_0402_5%  [R0402_0OHM]  111.99 112.59 270 top
PR1119  0_0402_5%  [R0402_0OHM]  112.97 112.59 270 top
PR1120  11K_0402_1%  [R_0402]  123.41 110.41 180 bottom
PR1121  2.61K_0402_1%  [R_0402]  114.07 93.55 0 bottom
PR1122  4.99K_0402_1%  [R_0402]  120.31 86.93 0 bottom
PR1123  11K_0402_1%  [R_0402]  112.04 103.51 180 bottom
PR1124  2K_0402_1%  [R_0402]  123.05 107.63 0 top
PR1125  1K_0402_1%  [R_0402]  125.1 105.87 270 bottom
PR1126  4.42K_0402_1%  [R_0402]  122.56 105.79 0 bottom
PR1127  1K_0402_1%  [R_0402]  109.73 104.95 90 bottom
PR1128  2.8K_0402_1%  [R_0402]  122.56 106.74 0 bottom
PR1129  110K_0402_1%  [R_0402]  122.56 104.78 0 top
PR1130  301_0402_1%  [R_0402]  111.13 105.79 0 bottom
PR1131  45.3_0402_1%  [R_0402]  114.81 114.5 270 top
PR1132  0_0402_5%  [R0402_0OHM]  115.87 112.61 270 top
PR1133  536_0402_1%  [R_0402]  118.49 100.97 270 bottom
PR1134  11K_0402_1%  [R_0402]  119.86 98.78 270 bottom
PR1135  1K_0402_1%  [R_0402]  118.11 97.74 90 bottom
PR1136  4.99K_0402_1%  [R_0402]  147.45 102.72 180 bottom
PR1137  90.9K_0402_1%  [R_0402]  112.9 100.97 270 top
PR1138  27.4K_0402_1%  [R_0402]  113.67 99.19 0 top
PR1139  2K_0402_1%  [R_0402]  116.59 100.97 270 top
PR1140  1K_0402_1%  [R_0402]  117.48 100.95 270 bottom
PR1141  2.26K_0402_1%  [R_0402]  115.7 100.97 270 bottom
PR1142  3.4K_0402_1%  [R_0402]  116.59 100.05 90 bottom
PR1143  2K_0402_1%  [R_0402]  109.55 107.7 180 top
PR1144  10.2K_0402_1%  [R_0402]  114.75 100.05 90 top
PR1145  100_0402_1%  [R_0402]  116.65 114.5 270 top
PR1200  10_1206_5%  [R_1206]  144.59 110.13 90 top
PR1201  100K_0402_1%  [R_0402]  128.27 100.27 180 bottom
PR1202  3.65K_0603_1%  [R_0603]  129.2 99.75 0 bottom
PR1203  2.2_0402_1%  [R_0402]  127.38 99.32 0 bottom
PR1204  10_1206_5%  [R_1206]  150 112.47 180 top
PR1205  100K_0402_1%  [R_0402]  128.27 102.43 180 bottom
PR1206  3.65K_0603_1%  [R_0603]  129.2 101 0 bottom
PR1207  2.2_0402_1%  [R_0402]  127.38 101.47 0 bottom
PR1208  10_1206_5%  [R_1206]  159.85 111.95 180 top
PR1209  100K_0402_1%  [R_0402]  128.08 98.24 180 bottom
PR1210  3.65K_0603_1%  [R_0603]  128.98 97.5 0 bottom
PR1211  2.2_0402_1%  [R_0402]  127.15 97.33 0 bottom
PR1212  100K_0402_1%  [R_0402]  125.73 100.27 180 bottom
PR1213  100K_0402_1%  [R_0402]  125.73 99.32 180 bottom
PR1214  100K_0402_1%  [R_0402]  125.73 102.17 180 bottom
PR1215  100K_0402_1%  [R_0402]  125.73 101.22 180 bottom
PR1216  100K_0402_1%  [R_0402]  125.67 97.27 180 bottom
PR1217  100K_0402_1%  [R_0402]  125.67 98.05 180 bottom
PR1218  0_0402_5%  [R0402_0OHM-NPM]  145.55 110.78 270 bottom
PR1219  0_0402_5%  [R0402_0OHM-NPM]  145.56 106.53 90 bottom
PR1220  0_0402_5%  [R0402_0OHM-NPM]  152.97 110.68 270 bottom
PR1221  0_0402_5%  [R0402_0OHM-NPM]  152.98 106.4 90 bottom
PR1222  0_0402_5%  [R0402_0OHM-NPM]  160.12 110.27 270 bottom
PR1223  0_0402_5%  [R0402_0OHM-NPM]  160.11 106.09 90 bottom
PR1224  3.9_0402_1%  [R_0402]  135.48 114.03 90 bottom
PR1225  3.9_0402_1%  [R_0402]  149.51 120.38 0 bottom
PR1226  3.9_0402_1%  [R_0402]  158.88 119.76 90 bottom
PR1300  4.7_1206_5%  [R_1206]  111.63 81.79 270 top
PR1301  3.65K_0603_1%  [R_0603]  105.92 102.49 90 top
PR1302  2.2_0402_1%  [R_0402]  109.22 103.33 270 top
PR1303  100K_0402_1%  [R_0402]  105.98 102.68 90 bottom
PR1304  2.2_0402_1%  [R_0402]  108.27 102.41 90 top
PR1305  3.65K_0603_1%  [R_0603]  107.19 102.49 90 top
PR1306  100K_0402_1%  [R_0402]  107.19 102.68 90 bottom
PR1307  4.7_1206_5%  [R_1206]  112.02 69.91 90 top
PR1308  4.7_1206_5%  [R_1206]  105.54 88.2 90 bottom
PR1309  3.65K_0603_1%  [R_0603]  125.99 104.65 90 top
PR1311  0_0402_5%  [R0402_0OHM]  115.46 96.01 90 top
PR1312  0_0402_5%  [R0402_0OHM-NPM]  114 82.98 0 bottom
PR1313  0_0402_5%  [R0402_0OHM-NPM]  118.06 82.98 180 bottom
PR1314  0_0402_5%  [R0402_0OHM-NPM]  113.11 70.74 0 bottom
PR1315  0_0402_5%  [R0402_0OHM-NPM]  117.18 70.74 180 bottom
PR1318  10_0402_1%  [R_0402]  116.65 112.6 270 top
PR1319  49.9_0402_1%  [R_0402]  115.05 112.29 270 top
PR1320  2.2_0402_1%  [R_0402]  104.04 82.34 270 bottom
PR1321  2.2_0402_1%  [R_0402]  103.96 77.76 270 bottom
PR1500  10K_0402_1%  [R_0402]  187.3 112.33 90 bottom
PR1501  0_0402_5%  [R_0402]  188.06 113.24 270 bottom
PR1502  8.2K_0402_1%  [R_0402]  188.82 113.24 270 bottom
PR1503  0_0402_5%  [R0402_0OHM]  185.57 113.16 0 bottom
PR1505  20.5K_0402_1%  [R_0402]  185.47 117.61 180 bottom
PR1507  6.19K_0402_1%  [R_0402]  185.14 114.69 0 bottom
PR1508  4.32K_0402_1%  [R_0402]  185.2 115.48 180 top
PR1509  16.5K_0402_1%  [R_0402]  185.34 114.56 0 top
PR1510  2.2_0603_5%  [R_0603]  190.69 112.27 0 bottom
PR1511  309_0402_1%  [R_0402]  187 115.57 0 top
PR1512  10_1206_5%  [R_1206]  190.18 101.92 90 top
PR1513  2.2_0603_5%  [R_0603]  193.74 119.38 180 bottom
PR1514  20_0402_1%  [R_0402]  182.7 118.04 0 bottom
PR1515  412K_0402_1%  [R_0402]  184.55 118.37 0 bottom
PR1516  100_0402_5%  [R_0402]  184.55 119.13 0 bottom
PR1517  0_0402_5%  [R0402_0OHM]  206.57 56.02 270 bottom
PR1518  0_0402_5%  [R0402_0OHM]  189.79 120.78 0 bottom
PR1519  71.5K_0402_1%  [R_0402]  189.04 119.11 90 bottom
PR1520  0_0402_5%  [R0402_0OHM]  207.52 56.02 270 bottom
PR1521  100_0402_5%  [R_0402]  185.7 120.02 0 bottom
PR1522  10K_0402_5%  [R_0402]  189.92 119.13 0 bottom
PR1600  0_0402_5%  [R0402_0OHM]  242.98 104.12 270 bottom
PR1601  4.7_1206_5%  [R_1206]  241.3 102.05 270 bottom
PR1602  0_0402_5%  [R0402_0OHM]  249.76 107.95 180 bottom
PR1603  100_0402_1%  [R_0402]  248.8 100.52 0 bottom
PR1604  1M_0402_1%  [R_0402]  248.84 107.19 0 bottom
PR1605  49.9K_0402_1%  [R_0402]  249.76 102.34 270 bottom
PR1606  100K_0402_5%  [R_0402]  249.51 104.66 180 bottom
PR1607  0_0402_5%  [R0402_0OHM]  248.59 103.9 0 bottom
PR1608  24K_0402_1%  [R_0402]  248.54 103.13 0 bottom
PR1643  100K_0402_5%  [R_0402]  247.91 106.48 90 top
PR1651  0_0402_5%  [R0402_0OHM]  248.67 107.39 270 top
PR1800  100K_0402_5%  [R_0402]  178.86 14.7 180 top
PR1801  0_0402_5%  [R0402_0OHM]  181.61 9.15 180 top
PR1803  21.5K_0402_1%  [R_0402]  180.75 15.72 180 top
PR1804  10K_0402_1%  [R_0402]  178.94 16.61 270 top
PR1805  0.01_0603_1%  [R_0603]  181.37 17.72 180 top
PR1851  0_0402_5%  [R0402_0OHM]  178.84 13.84 180 top
PR1900  0.01_1206_1%  [R_1206_4P-D]  57.15 11.82 270 bottom
PR1901  2_0603_1%  [R_0603]  49.66 8.57 90 top
PR1902  2_0603_1%  [R_0603]  46.61 8.7 90 top
PR1903  0_0603_5%  [R0603_0OHM]  52.13 9.91 180 top
PR1904  442K_0402_1%  [R_0402]  55.12 12.62 90 bottom
PR1905  2.2_0603_5%  [R_0603]  45.34 8.7 90 top
PR1906  100K_0402_5%  [R_0402]  54.36 13.54 270 bottom
PR1907  1_0805_5%~D  [R_0805]  53.84 13.54 0 top
PR1908  4.7_0402_5%  [R_0402]  42.62 11.05 180 top
PR1909  0_0402_5%  [R0402_0OHM]  54.88 15.69 180 top
PR1910  0.005_1206_1%  [R_1206_4P-D]  31.45 24.26 180 bottom
PR1911  100K_0402_1%  [R_0402]  55.77 20.77 180 top
PR1912  0_0402_5%  [R_0402]  53.14 14.86 90 top
PR1913  0_0402_5%  [R0402_0OHM]  54.88 16.51 180 top
PR1914  2.2_0603_5%  [R_0603]  42.1 13.72 0 top
PR1915  4.7_1206_5%  [R_1206]  40.51 4.95 180 top
PR1916  4.7_1206_5%  [R_1206]  36.26 14.54 180 top
PR1917  0_0402_5%  [R0402_0OHM]  54.88 17.27 180 top
PR1918  154K_0402_1%  [R_0402]  55.12 21.96 90 top
PR1919  0_0402_5%  [R0402_0OHM]  54.88 18.04 180 top
PR1920  1M_0402_1%  [R_0402]  56.77 24.22 180 top
PR1921  0_0402_5%  [R0402_0OHM]  54.88 18.8 180 top
PR1922  0_0402_5%  [R0402_0OHM]  43.35 15.63 0 top
PR1923  100K_0402_1%  [R_0402]  52.69 20.64 0 top
PR1924  100K_0402_1%  [R_0402]  51.88 20.65 270 top
PR1925  105K_0402_1%  [R_0402]  49.59 19.74 90 top
PR1926  100K_0402_1%  [R_0402]  51.12 20.65 270 top
PR1927  1K_0402_5%  [R_0402]  47.59 18.96 180 top
PR1928  0_0402_5%  [R0402_0OHM]  50.36 20.65 270 top
PR1929  0_0402_5%  [R0402_0OHM]  43.56 20.45 90 top
PR1930  0_0402_5%  [R0402_0OHM]  47.83 19.75 0 top
PR1931  1_0402_1%  [R_0402]  42.37 16.77 180 top
PR1932  0_0402_5%  [R0402_0OHM]  46.1 20.5 90 top
PR1933  0_0402_5%  [R0402_0OHM]  46.93 20.5 90 top
PR1934  10K_0402_5%  [R_0402]  44.39 20.5 90 top
PR1935  1_0402_1%  [R_0402]  42.37 17.53 180 top
PR1936  0_0402_5%  [R_0402]  61.22 14.1 90 top
PR1937  0_0402_5%  [R0402_0OHM]  63.4 8.85 0 top
PR1938  100_0402_1%  [R_0402]  41.77 21.21 0 top
PR1939  0_0402_5%  [R0402_0OHM]  61.24 8.97 0 top
PR1940  0_0402_5%  [R0402_0OHM]  63.68 16.38 0 top
PR1941  0_0402_5%  [R0402_0OHM]  64.43 12.29 180 top
PR1942  100K_0402_1%  [R_0402]  64.58 15.63 270 top
PR1943  100K_0402_1%  [R_0402]  64.36 10.77 270 top
PR1950  0_0402_5%  [R0402_0OHM]  137.88 1.55 180 bottom
PR1951  0_0402_5%  [R0402_0OHM]  104.06 61.85 0 bottom
PT200  PAD~D  [TPC12]  24.65 9.97 180 top
PT201  PAD~D  [TPC12]  176.84 13.04 0 top
PT202  PAD~D  [TPC12]  104.1 63.09 0 top
PU200  -  [LM393DGKR_VSSOP8]  30.76 3.13 180 top
PU201  MC74VHC1G08DFT2G SC70 5P AND  [TC7SH08FU_SSOP5]  18.1 33.67 270 bottom
PU202  MC74VHC1G08DFT2G SC70 5P AND  [TC7SH08FU_SSOP5]  22.47 17.59 0 top
PU203  -  [LM393DGKR_VSSOP8]  23.26 7.15 180 top
PU204  -  [RT9069-33GB_SOT23-5]  68.2 28.07 315 top
PU400  -  [TPS51285BRUKR_QFN20_3X3]  345.95 20 180 top
PU500  -  [SY8288RAC_QFN20_3X3]  132.64 8.45 270 bottom
PU600  -  [G5616ARZ1U_TQFN20_3X3]  287.47 31.62 0 bottom
PU700  RT8812AGQW-GP  [RT8812AGQW_WQFN20_3X3-S]  195.48 116.17 90 top
PU800  -  [SY8286RAC_QFN20_3X3]  108.84 60.14 90 bottom
PU900  -  [SY8286RAC_QFN20_3X3]  240.66 116.49 270 bottom
PU1001  -  [RT8816AGQW_WQFN20_3X3]  166.57 114.86 90 bottom
PU1100  -  [ISL95829AHRTZ-T_TQFN48_6X6]  114.05 108.59 0 top
PU1200  -  [FDMF3035_PQFN31_5X5]  136.66 111.94 90 bottom
PU1201  -  [FDMF3035_PQFN31_5X5]  147.77 119.24 0 bottom
PU1202  -  [FDMF3035_PQFN31_5X5]  156.96 118.62 0 bottom
PU1300  -  [AOZ5029QI_QFN24_5X3P5]  105.35 80.84 90 bottom
PU1301  -  [AOZ5029QI_QFN24_5X3P5]  104.59 72.96 90 bottom
PU1302  -  [ISL95808HRZ-TS2378_DFN8_2X2]  115.73 95.95 270 bottom
PU1501  -  [RT8816AGQW_WQFN20_3X3]  189.7 114.74 180 bottom
PU1600  -  [SY8286RAC_QFN20_3X3]  244.23 103.85 0 bottom
PU1800  -  [RT9059GQW_WDFN10_3X3]  182.03 14.37 180 top
PU1900  S IC ISL88738HRTZ-T TQFN 32P PWM  [ISL88738HRTZ-T_TQFN32_4X4]  46.86 16.51 0 top
PU1901  MC74VHC1G08DFT2G SC70 5P AND  [TC7SH08FU_SSOP5]  62.28 13.47 0 top
Q4  -  [L2N7002WT1G_SC-70-3]  341.5 103.82 0 top
Q5  -  [DMN66D0LDW-7_SOT363-6]  275.02 26.31 270 top
Q6  -  [L2N7002WT1G_SC-70-3]  310.9 35.75 180 bottom
QE2  -  [DMN65D8LDW-7_SOT363-6]  196.22 11.33 0 top
QE4  -  [DMN65D8LDW-7_SOT363-6]  286.95 3.8 90 top
QE5  -  [MMBT3904WH_SOT323-3]  174.79 117.65 0 bottom
QE6  -  [MMBT3904WH_SOT323-3]  189.41 51.47 0 top
QE7  -  [MMBT3904WH_SOT323-3]  112.56 111.91 270 bottom
QE8  -  [MMBT3904WH_SOT323-3]  179.83 50.03 180 bottom
QE9  -  [MMBT3904WH_SOT323-3]  241.11 107.88 0 bottom
QE10  -  [MMBT3904WH_SOT323-3]  300.42 5.12 0 top
QE11  -  [MMBT3904WH_SOT323-3]  29.59 49.24 90 bottom
QE12  -  [MMBT3904WH_SOT323-3]  281.47 28.61 180 bottom
QE13  -  [L2N7002WT1G_SC-70-3]  188.55 7.7 180 top
QE15  -  [MMBT3904WH_SOT323-3]  158.67 69.83 180 top
QE18  -  [DMN65D8LDW-7_SOT363-6]  286.95 6.72 90 top
QE20  -  [L2N7002WT1G_SC-70-3]  139.13 14.48 270 top
QF1  -  [DMN65D8LDW-7_SOT363-6]  234 44.21 270 top
QH1  -  [LP2301ALT1G_SOT23-3]  141.86 12.45 0 top
QH3  -  [2N7002KDW_SOT363-6]  348.23 84.15 0 top
QH4  -  [DMN65D8LDW-7_SOT363-6]  110.42 10.81 270 bottom
QH5  -  [2N7002KDW_SOT363-6]  347.01 86.33 180 top
QI10  -  [L2N7002WT1G_SC-70-3]  326.9 44.64 180 top
QR1  -  [L2N7002WT1G_SC-70-3]  348.24 32.7 180 bottom
QR104  -  [L2N7002WT1G_SC-70-3]  176.91 9.78 0 top
QR105  -  [L2N7002WT1G_SC-70-3]  333.25 42.74 0 bottom
QRTC  -  [LP2301ALT1G_SOT23-3]  171.45 6.86 270 top
QRTC1  -  [DMN65D8LW-7_SOT323-3]  178.7 4.53 90 top
QV3  DMN63D8LDW-7_SOT363-6  [DMN65D8LDW-7_SOT363-6]  249.1 46.99 0 top
QV11  SI3457BDV-T1-E3_TSOP6~D  [SI3457BDV-T1-E3_TSOP6]  46.09 34.49 180 top
QV12  -  [L2N7002WT1G_SC-70-3]  39.3 34.14 270 top
QV21  -  [DMN63D8LDW-7_SOT363-6]  201.74 46.26 180 top
QV89  -  [L2N7002WT1G_SC-70-3]  26.42 52.14 180 top
QV91  BSS138W 1N SOT-323-3  [2N7002W-T-R7_SOT323-3]  216.65 43.22 270 top
QV98  BSS138W 1N SOT-323-3  [2N7002W-T-R7_SOT323-3]  244.06 49.55 180 top
QV101  BSS138W 1N SOT-323-3  [2N7002W-T-R7_SOT323-3]  220.13 107.24 90 top
QV102  BSS138W 1N SOT-323-3  [2N7002W-T-R7_SOT323-3]  244.73 93.5 90 top
QV103  BSS138W 1N SOT-323-3  [2N7002W-T-R7_SOT323-3]  198.63 49.75 0 top
QV105  BSS138W 1N SOT-323-3  [2N7002W-T-R7_SOT323-3]  229.94 44.34 180 top
QZ6  DMN63D8LDW-7_SOT363-6  [DMN65D8LDW-7_SOT363-6]  251.57 53.53 0 top
QZ9  -  [DMG2301U-7_SOT23-3]  54.1 25.93 0 bottom
QZ14  DMN63D8LDW-7 2N SOT363-6  [DMN65D8LDW-7_SOT363-6]  223.19 118.24 90 top
QZ15  DMN63D8LDW-7 2N SOT363-6  [DMN65D8LDW-7_SOT363-6]  166.59 117.4 0 top
QZ17  DMN63D8LDW-7 2N SOT363-6  [DMN65D8LDW-7_SOT363-6]  252.1 43.05 0 top
QZ18  -  [L2N7002WT1G_SC-70-3]  221.62 113.61 180 top
R3  1M_0402_5%~D  [R_0402]  172.84 4.32 0 top
R276  10K_0201_5%  [R_0201]  170.46 5.32 270 top
R277  100K_0201_1%  [R_0201]  175.08 6.73 270 top
R281  0438.500WR 0.5A 32V UL/CSA  [R_0603]  315.22 31.69 270 bottom
R5831  24.9_0402_1%  [R_0402]  312.34 20.07 0 top
R5832  499K_0402_1%  [R_0402]  145.29 15.01 180 top
R5841  0_0201_5%  [R_0201]  319.91 37.89 270 bottom
R5842  200K_0402_1%  [R_0402]  278.84 25.91 180 top
R5843  33_0402_1%  [R_0402]  274.07 24.94 90 top
RA2  0_0603_5%  [R0603_0OHM]  2.91 31.22 90 top
RA4  200K_0201_1%  [R_0201]  2.82 28.56 180 top
RA6  33_0201_5%  [R_0201]  2.41 30.06 90 bottom
RA7  200K_0201_1%  [R_0201]  2.82 27.98 180 top
RA12  10K_0201_5%  [R_0201]  15.72 36.77 180 bottom
RA13  100K_0201_1%  [R_0201]  7.07 33.24 0 bottom
RA14  200K_0201_1%  [R_0201]  7.07 33.87 0 bottom
RA15  100K_0201_1%  [R_0201]  11.18 33.16 90 bottom
RA16  100K_0201_1%  [R_0201]  10.1 33.11 90 bottom
RA17  4.7K_0201_5%  [R_0201]  4.04 29.05 90 bottom
RA18  0_0603_5%  [R0603_0OHM]  4.65 30.37 270 top
RA19  2.2K_0402_5%~D  [R_0402]  9.98 45.4 180 top
RA20  2.2K_0402_5%~D  [R_0402]  11.96 59.12 0 bottom
RA21  2.2K_0402_5%~D  [R_0402]  10.62 59.12 180 bottom
RA27  4.7K_0402_5%~D  [R_0402]  11.95 41.97 180 top
RA28  4.7K_0402_5%~D  [R_0402]  13.86 45.34 180 top
RA29  4.7K_0402_5%~D  [R_0402]  11.43 43.77 270 top
RA30  1K_0402_5%~D  [R_0402]  10.1 43.77 270 top
RA31  1K_0402_5%~D  [R_0402]  9.39 41.97 0 top
RA51  2.4_0402_5%  [R_0402]  14.16 49.43 0 top
RA52  2.4_0402_5%  [R_0402]  13.88 48.25 90 bottom
RA57  10K_0201_5%  [R_0201]  2.24 29.13 0 top
RA68  10K_0201_5%  [R_0201]  13.89 37.23 315 bottom
RA73  0_0603_5%  [R_0603]  5.39 40.08 0 top
RA74  0_0603_5%  [R0603_0OHM]  12.17 39.68 90 top
RA75  4.7K_0402_5%~D  [R_0402]  10.76 45.43 0 top
RA82  100K_0201_5%  [R_0201]  4.97 45.25 180 bottom
RA93  0_0402_5%~D  [R_0402]  4.57 30.4 90 bottom
RA94  0_0402_1%  [R0402_0OHM]  2.36 31.67 90 bottom
RA95  0_0402_5%  [R_0402]  2.92 59.79 270 bottom
RA96  33_0201_5%  [R_0201]  102.11 17.65 180 top
RA97  33_0201_5%  [R_0201]  102.11 18.24 180 top
RA98  33_0201_5%  [R_0201]  22.73 33.02 270 bottom
RA99  33_0201_5%  [R_0201]  22.73 31.17 90 bottom
RA100  0_0402_5%  [R_0402]  7.85 32.86 90 top
RA101  0_0402_5%  [R_0402]  9.75 33.28 180 top
RA102  33_0402_5%  [R_0402]  151.17 7.55 270 bottom
RA103  33_0402_5%  [R_0402]  148.22 9.46 270 bottom
RC183  499_0402_1%  [R_0402]  341.31 42.41 90 bottom
RC184  499_0402_1%  [R_0402]  342.14 42.41 90 bottom
RC5831  15_0201_1%  [R_0201]  113.72 9.27 0 top
RC5832  15_0201_1%  [R_0201]  113.67 10.92 0 top
RC5833  15_0201_1%  [R_0201]  113.72 11.69 0 top
RC5834  15_0201_1%  [R_0201]  113.72 10.03 0 top
RC5835  100K_0402_5%  [R_0402]  345.36 45.82 270 bottom
RD1  0_0402_5%  [R_0402]  171.34 20.28 0 top
RD2  0_0402_5%  [R_0402]  173.6 25.67 0 top
RD3  0_0402_5%  [R_0402]  152.45 18.31 180 top
RD4  0_0402_5%  [R_0402]  248.81 19.31 90 top
RD5  0_0402_1%  [R0402_0OHM]  248.82 17.54 0 top
RD6  0_0402_5%  [R_0402]  228.3 16.87 180 top
RD7  10K_0402_5%  [R_0402]  268.48 13.39 180 top
RD8  10K_0402_5%  [R_0402]  267.51 9.78 0 top
RD9  0_0402_5%  [R_0402]  268.43 6.86 180 top
RD10  10K_0402_5%  [R_0402]  256.27 4.45 0 bottom
RD28  0_0402_1%  [R0402_0OHM]  172.25 19.39 180 top
RD29  0_0402_1%  [R0402_0OHM]  176.12 24.71 0 top
RD30  0_0402_1%  [R0402_0OHM]  151.19 19.15 90 top
RD35  470_0402_1%  [R_0402]  136.91 17.53 180 top
RD38  0_0402_1%  [R0402_0OHM]  247.71 19.55 180 top
RD39  0_0402_5%  [R_0402]  249.72 16.73 180 top
RD40  0_0402_1%  [R0402_0OHM]  227.38 17.68 0 top
RD58  0_0402_1%  [R0402_0OHM]  254.5 4.45 0 bottom
RD59  0_0402_5%  [R_0402]  267.51 8.83 0 top
RD100  0_0402_5%  [R_0402]  237.92 9.15 0 top
RD101  0_0402_5%  [R_0402]  267.64 20.96 0 top
RD102  0_0402_1%  [R0402_0OHM]  134.33 17.53 0 top
RE3  300_0402_5%  [R_0402]  334.42 107.46 90 top
RE7  2.4K_0402_5%  [R_0402]  191.66 11.56 180 top
RE9  2.4K_0402_5%  [R_0402]  197.41 14.54 180 top
RE16  0_0603_5%  [R0603_0OHM]  281.51 16.63 0 top
RE19  10K_0402_5%  [R_0402]  306.33 23.75 0 top
RE20  2.2K_0402_5%  [R_0402]  296.04 25.78 90 top
RE21  2.2K_0402_5%  [R_0402]  295.4 22.86 0 top
RE22  10K_0402_5%  [R_0402]  306.5 11.05 0 top
RE23  10K_0402_5%  [R_0402]  306.5 10.16 0 top
RE24  4.7K_0402_5%  [R_0402]  194.06 14.35 180 bottom
RE25  10K_0402_5%  [R_0402]  290.7 22.1 180 top
RE26  4.7K_0402_5%  [R_0402]  191.39 14.35 0 bottom
RE27  10K_0402_5%  [R_0402]  303.56 28.45 270 top
RE30  100K_0402_5%  [R_0402]  309.42 19.81 0 top
RE31  10K_0402_5%  [R_0402]  309.5 3.23 90 top
RE32  100K_0402_5%  [R_0402]  310.4 10.29 180 top
RE33  1M_0402_5%  [R_0402]  303.02 3.93 90 top
RE34  100K_0402_5%  [R_0402]  287.45 16.13 0 top
RE35  0_0402_5%  [R_0402]  302.9 23.24 270 top
RE36  1K_0402_5%  [R_0402]  288.37 18.16 180 top
RE38  0_0402_5%  [R_0402]  310.34 20.83 180 top
RE39  0_0402_1%  [R0402_0OHM]  310.34 21.85 180 top
RE41  100K_0402_5%  [R_0402]  307.29 21.15 180 top
RE43  1K_0402_5%  [R_0402]  293.6 4.95 270 top
RE44  100K_0402_5%  [R_0402]  294.49 4.04 90 top
RE45  10_0402_5%  [R_0402]  307.29 20.32 180 top
RE48  33_0402_1%  [R_0402]  304.17 25.32 90 top
RE50  100K_0402_5%  [R_0402]  290.06 4.94 0 top
RE51  0_0402_1%  [R0402_0OHM]  291.59 10.08 90 top
RE52  10K_0402_5%  [R_0402]  288.75 5.08 180 top
RE54  10K_0402_5%  [R_0402]  291.72 4.95 270 top
RE55  300_0402_5%  [R_0402]  310.39 7.75 180 top
RE56  100K_0402_5%  [R_0402]  283.1 3.75 0 top
RE58  1.33K_0402_1%  [R_0402]  288.37 20.19 180 top
RE59  100K_0402_5%  [R_0402]  298.25 25.78 0 top
RE60  49.9_0402_1%  [R_0402]  313.18 28.63 90 top
RE61  100_0402_1%  [R_0402]  299.16 23.6 180 top
RE62  10_0402_5%  [R_0402]  294.91 33.47 180 top
RE63  10K_0402_5%  [R_0402]  307.72 28.25 90 top
RE64  10K_0402_5%  [R_0402]  306.83 27.38 270 top
RE65  100K_0402_5%  [R_0402]  306.83 28.25 90 top
RE66  8.2K_0402_5%  [R_0402]  302.62 6.67 90 top
RE67  8.2K_0402_1%  [R_0402]  301.76 22.48 90 top
RE68  10K_0402_5%  [R_0402]  300.36 26.29 270 top
RE69  2.2K_0402_5%  [R_0402]  302.13 3.93 90 top
RE70  10K_0402_5%  [R_0402]  301.25 26.29 270 top
RE71  100K_0402_5%  [R_0402]  303.79 23.32 270 top
RE72  100K_0402_5%  [R_0402]  296.05 6.74 90 top
RE81  100K_0201_5%  [R_0201]  100.71 36.49 270 top
RE82  10K_0201_5%  [R_0201]  97.96 34.56 90 top
RE83  100K_0201_5%  [R_0201]  334.24 47.64 90 bottom
